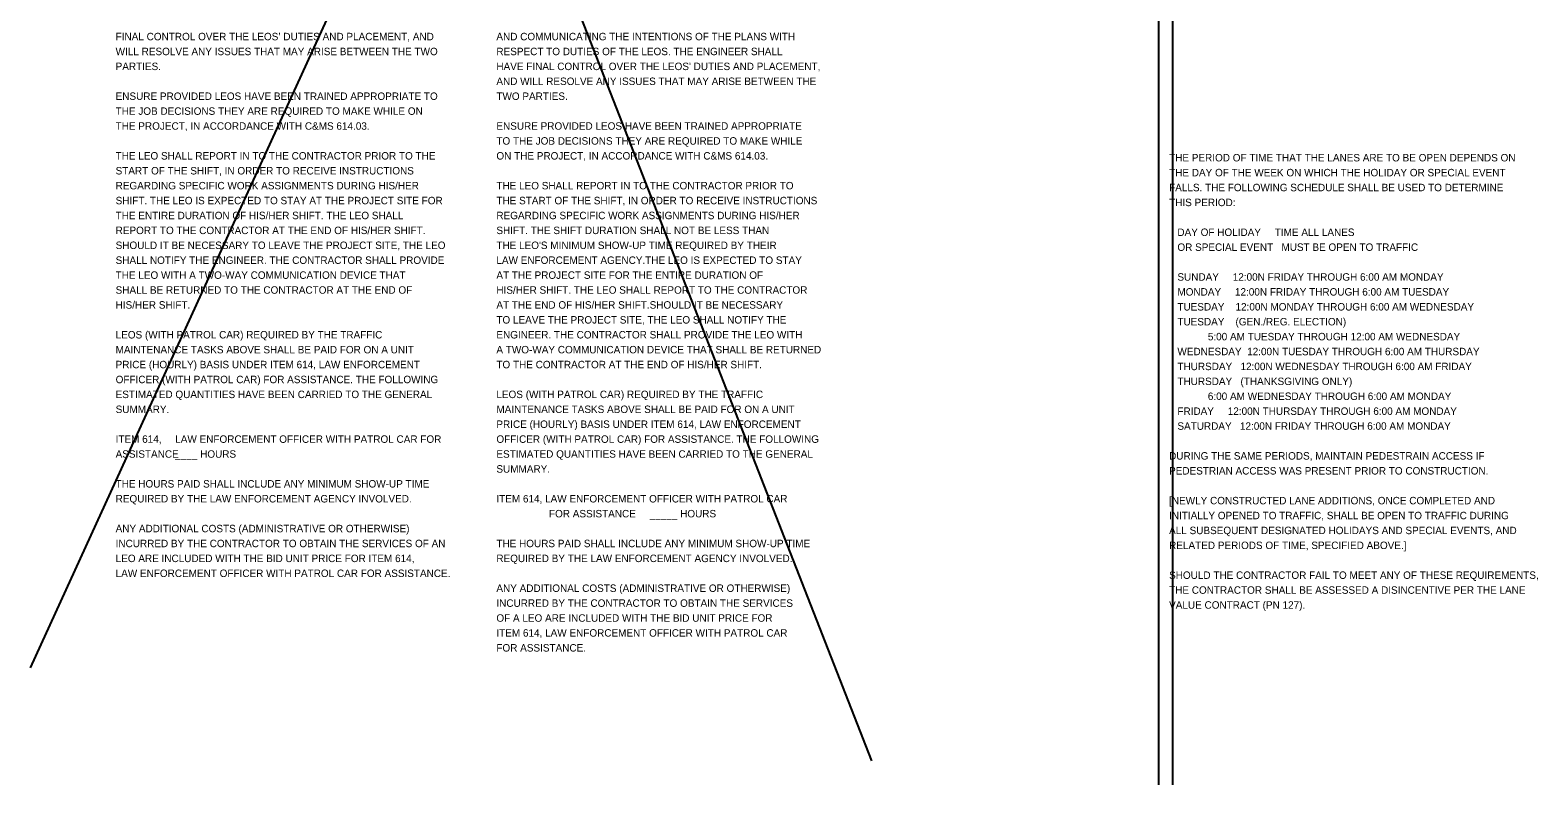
# Model space of a CAD drawing. Extents: x -18.5 to 46, y -14.2 to 42.5.
# Drawn here: x -18.54 to 9.8, y -14.22 to -0.05 of the extents above; entities that cross this region are included whole.
import ezdxf

# ---------------------------------------------------------------- set-up
doc = ezdxf.new("R2010")
doc.units = 0
doc.layers.add('SN_X_Public', color=7, linetype='Continuous')

msp = doc.modelspace()

# ---------------------------------------------------------------- linework, layer by layer
at = {"layer": 'SN_X_Public'}
for p, q in [((-2.978, 21.996), (-18.545, -12.023)), ((-16.677, 21.872), (-2.729, -13.768)), ((2.664, 14.14), (2.664, -14.22)), ((2.928, 14.14), (2.928, -14.22))]:
    msp.add_line(p, q, dxfattribs=at)

# ---------------------------------------------------------------- texts
for s, p in [('FINAL CONTROL OVER THE LEOS’ DUTIES AND PLACEMENT, AND ', (-16.938, -0.237)), ('AND COMMUNICATING THE INTENTIONS OF THE PLANS WITH', (-9.781, -0.237)), ('WILL RESOLVE ANY ISSUES THAT MAY ARISE BETWEEN THE TWO ', (-16.938, -0.517)), ('RESPECT TO DUTIES OF THE LEOS. THE ENGINEER SHALL', (-9.781, -0.517)), ('PARTIES. ', (-16.938, -0.797)), ("HAVE FINAL CONTROL OVER THE LEOS' DUTIES AND PLACEMENT,", (-9.781, -0.797)), ('AND WILL RESOLVE ANY ISSUES THAT MAY ARISE BETWEEN THE', (-9.781, -1.077)), ('ENSURE PROVIDED LEOS HAVE BEEN TRAINED APPROPRIATE TO ', (-16.938, -1.357)), ('TWO PARTIES.', (-9.781, -1.357)), ('THE JOB DECISIONS THEY ARE REQUIRED TO MAKE WHILE ON ', (-16.938, -1.637)), ('THE PROJECT, IN ACCORDANCE WITH C&MS 614.03.', (-16.938, -1.917)), ('ENSURE PROVIDED LEOS HAVE BEEN TRAINED APPROPRIATE', (-9.781, -1.917)), ('TO THE JOB DECISIONS THEY ARE REQUIRED TO MAKE WHILE', (-9.781, -2.197)), ('THE LEO SHALL REPORT IN TO THE CONTRACTOR PRIOR TO THE ', (-16.938, -2.477)), ('ON THE PROJECT, IN ACCORDANCE WITH C&MS 614.03.', (-9.781, -2.477)), ('THE PERIOD OF TIME THAT THE LANES ARE TO BE OPEN DEPENDS ON', (2.864, -2.512)), ('START OF THE SHIFT, IN ORDER TO RECEIVE INSTRUCTIONS ', (-16.938, -2.757)), ('THE DAY OF THE WEEK ON WHICH THE HOLIDAY OR SPECIAL EVENT', (2.864, -2.792)), ('REGARDING SPECIFIC WORK ASSIGNMENTS DURING HIS/HER ', (-16.938, -3.037)), ('THE LEO SHALL REPORT IN TO THE CONTRACTOR PRIOR TO', (-9.781, -3.037)), ('FALLS. THE FOLLOWING SCHEDULE SHALL BE USED TO DETERMINE', (2.864, -3.072)), ('SHIFT. THE LEO IS EXPECTED TO STAY AT THE PROJECT SITE FOR ', (-16.938, -3.317)), ('THE START OF THE SHIFT, IN ORDER TO RECEIVE INSTRUCTIONS', (-9.781, -3.317)), ('THIS PERIOD:', (2.864, -3.352)), ('THE ENTIRE DURATION OF HIS/HER SHIFT. THE LEO SHALL ', (-16.938, -3.597)), ('REGARDING SPECIFIC WORK ASSIGNMENTS DURING HIS/HER', (-9.781, -3.597)), ('REPORT TO THE CONTRACTOR AT THE END OF HIS/HER SHIFT. ', (-16.938, -3.877)), ('SHIFT. THE SHIFT DURATION SHALL NOT BE LESS THAN', (-9.781, -3.877)), ('   DAY OF HOLIDAY     TIME ALL LANES', (2.864, -3.912)), ('SHOULD IT BE NECESSARY TO LEAVE THE PROJECT SITE, THE LEO ', (-16.938, -4.157)), ("THE LEO'S MINIMUM SHOW-UP TIME REQUIRED BY THEIR", (-9.781, -4.157)), ('   OR SPECIAL EVENT   MUST BE OPEN TO TRAFFIC', (2.864, -4.192)), ('SHALL NOTIFY THE ENGINEER. THE CONTRACTOR SHALL PROVIDE ', (-16.938, -4.437)), ('LAW ENFORCEMENT AGENCY.THE LEO IS EXPECTED TO STAY', (-9.781, -4.437)), ('THE LEO WITH A TWO-WAY COMMUNICATION DEVICE THAT ', (-16.938, -4.717)), ('AT THE PROJECT SITE FOR THE ENTIRE DURATION OF', (-9.781, -4.717)), ('   SUNDAY     12:00N FRIDAY THROUGH 6:00 AM MONDAY', (2.864, -4.752)), ('SHALL BE RETURNED TO THE CONTRACTOR AT THE END OF ', (-16.938, -4.997)), ('HIS/HER SHIFT. THE LEO SHALL REPORT TO THE CONTRACTOR', (-9.781, -4.997)), ('   MONDAY     12:00N FRIDAY THROUGH 6:00 AM TUESDAY', (2.864, -5.032)), ('HIS/HER SHIFT. ', (-16.938, -5.277)), ('AT THE END OF HIS/HER SHIFT.SHOULD IT BE NECESSARY', (-9.781, -5.277)), ('   TUESDAY    12:00N MONDAY THROUGH 6:00 AM WEDNESDAY', (2.864, -5.312)), ('TO LEAVE THE PROJECT SITE, THE LEO SHALL NOTIFY THE', (-9.781, -5.557)), ('   TUESDAY    (GEN./REG. ELECTION)', (2.864, -5.592)), ('LEOS (WITH PATROL CAR) REQUIRED BY THE TRAFFIC ', (-16.938, -5.837)), ('ENGINEER. THE CONTRACTOR SHALL PROVIDE THE LEO WITH', (-9.781, -5.837)), ('              5:00 AM TUESDAY THROUGH 12:00 AM WEDNESDAY', (2.864, -5.872)), ('MAINTENANCE TASKS ABOVE SHALL BE PAID FOR ON A UNIT ', (-16.938, -6.117)), ('A TWO-WAY COMMUNICATION DEVICE THAT SHALL BE RETURNED', (-9.781, -6.117)), ('   WEDNESDAY  12:00N TUESDAY THROUGH 6:00 AM THURSDAY', (2.864, -6.152)), ('PRICE (HOURLY) BASIS UNDER ITEM 614, LAW ENFORCEMENT ', (-16.938, -6.397)), ('TO THE CONTRACTOR AT THE END OF HIS/HER SHIFT.', (-9.781, -6.397)), ('   THURSDAY   12:00N WEDNESDAY THROUGH 6:00 AM FRIDAY', (2.864, -6.432)), ('OFFICER (WITH PATROL CAR) FOR ASSISTANCE. THE FOLLOWING ', (-16.938, -6.677)), ('   THURSDAY   (THANKSGIVING ONLY)', (2.864, -6.712)), ('ESTIMATED QUANTITIES HAVE BEEN CARRIED TO THE GENERAL ', (-16.938, -6.957)), ('LEOS (WITH PATROL CAR) REQUIRED BY THE TRAFFIC', (-9.781, -6.957)), ('              6:00 AM WEDNESDAY THROUGH 6:00 AM MONDAY', (2.864, -6.992)), ('SUMMARY.', (-16.938, -7.237)), ('MAINTENANCE TASKS ABOVE SHALL BE PAID FOR ON A UNIT', (-9.781, -7.237)), ('   FRIDAY     12:00N THURSDAY THROUGH 6:00 AM MONDAY', (2.864, -7.272)), ('OFFICER (WITH PATROL CAR) FOR ASSISTANCE. THE FOLLOWING', (-9.781, -7.797)), ('PRICE (HOURLY) BASIS UNDER ITEM 614, LAW ENFORCEMENT', (-9.781, -7.517)), ('   SATURDAY   12:00N FRIDAY THROUGH 6:00 AM MONDAY', (2.864, -7.552)), ('ASSISTANCE', (-16.938, -8.077)), ('ITEM 614,  ', (-16.938, -7.797)), ('____ HOURS', (-15.818, -8.077)), ('LAW ENFORCEMENT OFFICER WITH PATROL CAR FOR ', (-15.818, -7.797)), ('ESTIMATED QUANTITIES HAVE BEEN CARRIED TO THE GENERAL', (-9.781, -8.077)), ('SUMMARY.', (-9.781, -8.357)), ('DURING THE SAME PERIODS, MAINTAIN PEDESTRAIN ACCESS IF', (2.864, -8.112)), ('THE HOURS PAID SHALL INCLUDE ANY MINIMUM SHOW-UP TIME ', (-16.938, -8.637)), ('PEDESTRIAN ACCESS WAS PRESENT PRIOR TO CONSTRUCTION.', (2.864, -8.392)), ('REQUIRED BY THE LAW ENFORCEMENT AGENCY INVOLVED.', (-16.938, -8.917)), ('ITEM 614, LAW ENFORCEMENT OFFICER WITH PATROL CAR', (-9.781, -8.917)), ('                   FOR ASSISTANCE     _____ HOURS', (-9.781, -9.197)), ('[NEWLY CONSTRUCTED LANE ADDITIONS, ONCE COMPLETED AND', (2.864, -8.952)), ('ANY ADDITIONAL COSTS (ADMINISTRATIVE OR OTHERWISE) ', (-16.938, -9.477)), ('INITIALLY OPENED TO TRAFFIC, SHALL BE OPEN TO TRAFFIC DURING', (2.864, -9.232)), ('INCURRED BY THE CONTRACTOR TO OBTAIN THE SERVICES OF AN ', (-16.938, -9.757)), ('THE HOURS PAID SHALL INCLUDE ANY MINIMUM SHOW-UP TIME', (-9.781, -9.757)), ('ALL SUBSEQUENT DESIGNATED HOLIDAYS AND SPECIAL EVENTS, AND', (2.864, -9.512)), ('LEO ARE INCLUDED WITH THE BID UNIT PRICE FOR ITEM 614, ', (-16.938, -10.037)), ('REQUIRED BY THE LAW ENFORCEMENT AGENCY INVOLVED.', (-9.781, -10.037)), ('RELATED PERIODS OF TIME, SPECIFIED ABOVE.]', (2.864, -9.792)), ('LAW ENFORCEMENT OFFICER WITH PATROL CAR FOR ASSISTANCE.', (-16.938, -10.317)), ('ANY ADDITIONAL COSTS (ADMINISTRATIVE OR OTHERWISE)', (-9.781, -10.597)), ('SHOULD THE CONTRACTOR FAIL TO MEET ANY OF THESE REQUIREMENTS,', (2.864, -10.352)), ('INCURRED BY THE CONTRACTOR TO OBTAIN THE SERVICES', (-9.781, -10.877)), ('VALUE CONTRACT (PN 127).', (2.864, -10.912)), ('THE CONTRACTOR SHALL BE ASSESSED A DISINCENTIVE PER THE LANE', (2.864, -10.632)), ('OF A LEO ARE INCLUDED WITH THE BID UNIT PRICE FOR', (-9.781, -11.157)), ('ITEM 614, LAW ENFORCEMENT OFFICER WITH PATROL CAR', (-9.781, -11.437)), ('FOR ASSISTANCE.', (-9.781, -11.717))]:
    msp.add_text(s, height=0.14, dxfattribs=at).set_placement(p)

doc.saveas('drawing.dxf')
